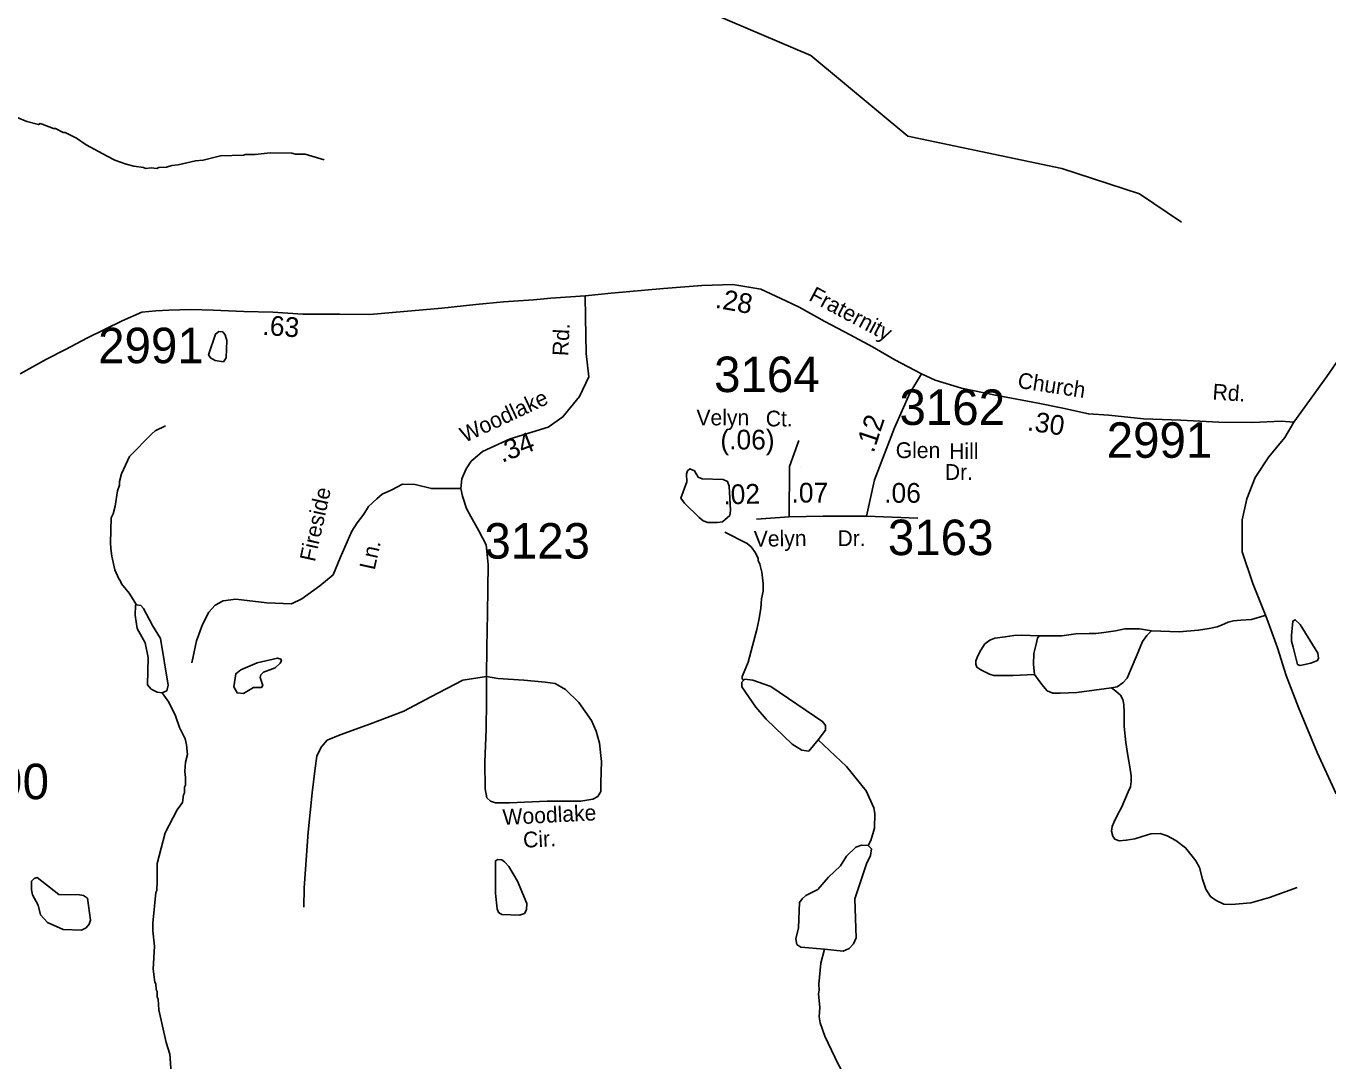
# Model space of a CAD drawing. Extents: x 1551653 to 1702041, y 811336 to 920032.
# Drawn here: x 1609613 to 1615028, y 824369 to 828674 of the extents above; entities that cross this region are included whole.
import ezdxf

# ---------------------------------------------------------------- set-up
doc = ezdxf.new("R2010")
doc.units = 0
for name, color, linetype in [('Old_Level_10', 7, 'Continuous'), ('Old_Level_11', 7, 'Continuous'), ('Old_Level_17', 7, 'Continuous'), ('Old_Level_32', 7, 'Continuous'), ('Old_Level_35', 7, 'Continuous'), ('Old_Level_59', 7, 'Continuous'), ('Old_Level_62', 7, 'Continuous'), ('Old_Level_8', 7, 'Continuous')]:
    doc.layers.add(name, color=color, linetype=linetype)

msp = doc.modelspace()

# ---------------------------------------------------------------- linework, layer by layer
at = {"layer": 'Old_Level_17'}
msp.add_line((1612833.711, 826837.728), (1612833.711, 826837.728), dxfattribs=at)
at = {"layer": 'Old_Level_32'}
for p, q in [((1612787.219, 826632.516), (1612651.564, 826622.461)), ((1613322.303, 826627.489), (1613108.771, 826635.03))]:
    msp.add_line(p, q, dxfattribs=at)
for points in [[(1615872.117, 828613.906), (1615854.48, 828536.257), (1615829.788, 828455.078), (1615794.515, 828359.782), (1615745.132, 828260.956), (1615678.112, 828169.189), (1615589.928, 828063.303), (1615494.689, 827904.476), (1615427.669, 827798.591), (1615367.704, 827696.236), (1615311.266, 827618.586), (1615247.773, 827540.937), (1615180.753, 827445.641), (1615022.93, 827216.627), (1614886.031, 827027.073)], [(1611938.181, 827552.387), (1612046.323, 827562.996), (1612264.726, 827582.091), (1612423.757, 827594.821), (1612552.228, 827599.231), (1612668.615, 827580.229), (1612772.516, 827531.429), (1612828.185, 827505.142), (1612935.979, 827444.947), (1613041.03, 827389.205), (1613134.284, 827340.088), (1613226.234, 827285.186), (1613337.763, 827228.028)], [(1609589.303, 827228.028), (1609698.111, 827287.909), (1609776.997, 827328.737), (1609869.485, 827377.731), (1610013.657, 827448.499), (1610095.263, 827483.884), (1610152.388, 827489.327), (1610206.792, 827492.05), (1610299.28, 827494.771), (1610391.767, 827492.05), (1610519.617, 827486.606), (1610639.307, 827483.884), (1610764.437, 827475.718), (1610916.657, 827476.121), (1611042.494, 827474.569), (1611184.416, 827486.699), (1611342.385, 827500.704), (1611484.206, 827516.546), (1611598.914, 827526.926), (1611724.019, 827535.413), (1611796.113, 827541.779), (1611938.181, 827552.387)], [(1611938.181, 827552.387), (1611940.302, 827463.276), (1611942.422, 827312.635), (1611953.695, 827214.515), (1611914.539, 827132.878), (1611846.035, 827048.437), (1611784.543, 827006.003), (1611627.393, 826956.542), (1611511.101, 826904.515), (1611480.557, 826878.17), (1611464.679, 826864.13), (1611443.475, 826832.304), (1611425.086, 826790.003), (1611421.585, 826750.94), (1611428.614, 826717.913), (1611444.801, 826667.296), (1611463.548, 826634.498), (1611496.873, 826574.481), (1611526.277, 826515.899), (1611535.221, 826433.872), (1611532.766, 826231.606), (1611529.503, 826087.925), (1611528.228, 825969.08)], [(1613337.763, 827228.028), (1613288.799, 827146.371), (1613225.698, 827003.045), (1613141.43, 826785.849), (1613108.771, 826635.03)], [(1613337.763, 827228.028), (1613394.887, 827200.808), (1613503.696, 827168.146), (1613645.148, 827138.206), (1613822.284, 827104.82), (1613925.884, 827084.458), (1614031.333, 827060.394), (1614116.433, 827054.84), (1614260.733, 827040.031), (1614416.132, 827034.478), (1614573.381, 827027.073), (1614713.981, 827025.222), (1614834.231, 827030.776), (1614886.031, 827027.073)], [(1614886.031, 827027.073), (1614849.03, 826963.024), (1614782.431, 826881.575), (1614725.081, 826796.424), (1614689.931, 826707.57), (1614671.432, 826620.568), (1614671.432, 826487.288), (1614715.831, 826355.858), (1614773.641, 826209.821), (1614817.978, 826087.253), (1614854.481, 825972.85), (1614905.849, 825840.126), (1614982.745, 825651.615), (1615061.564, 825480.416)], [(1612787.219, 826632.516), (1612789.028, 826842.25), (1612827.061, 826950.792)], [(1613108.771, 826635.03), (1612927.898, 826635.03), (1612787.219, 826632.516)]]:
    msp.add_lwpolyline(points, dxfattribs=at)
at = {"layer": 'Old_Level_35'}
for points in [[(1610302.502, 826024.762), (1610321.57, 826116.426), (1610346.557, 826184.158), (1610373.013, 826235.651), (1610399.431, 826265.33), (1610433.604, 826282.849), (1610485.582, 826290.198), (1610615.316, 826275.138), (1610716.996, 826271.194), (1610760.803, 826291.74), (1610834.48, 826345.898), (1610889.951, 826391.615), (1610920.197, 826461.39), (1610968.11, 826572.341), (1610990.116, 826607.486), (1611017.495, 826643.1), (1611038.065, 826675.454), (1611072.289, 826706.959), (1611093.813, 826726.675), (1611134.881, 826744.481), (1611179.044, 826768.255), (1611231.064, 826766.885), (1611299.511, 826750.448), (1611421.585, 826750.94)], [(1614770.826, 826223.843), (1614709.771, 826206.079), (1614665.15, 826202.073), (1614634.81, 826199.419), (1614613.308, 826194.72), (1614584.427, 826181.336), (1614566.429, 826174.752), (1614534.203, 826168.592), (1614489.476, 826161.026), (1614409.179, 826154.527), (1614293.579, 826157.99)], [(1614293.579, 826157.99), (1614243.996, 826166.6), (1614222.654, 826167.239), (1614183.475, 826166.632), (1614144.082, 826158.907), (1614095.797, 826151.448), (1614061.847, 826147.121), (1614035.17, 826147.921), (1613979.931, 826146.013), (1613920.922, 826137.094), (1613826.611, 826138.139)], [(1614128.046, 825920.715), (1614151.325, 825925.361), (1614174.978, 825942.464), (1614193.349, 825961.506), (1614206.811, 825994.944), (1614233.683, 826060.04), (1614256.677, 826114.567), (1614275.208, 826138.948), (1614293.579, 826157.99)], [(1613826.611, 826138.139), (1613751.916, 826140.377), (1613721.629, 826139.503), (1613685.846, 826133.451), (1613642.95, 826127.611), (1613621.342, 826119.353), (1613601.299, 826103.923), (1613584.493, 826077.709), (1613571.351, 826054.949), (1613563.598, 826033.807), (1613563.171, 826019.571), (1613568.133, 826006.954), (1613583.82, 825995.798), (1613620.687, 825978.663), (1613638.312, 825972.791), (1613661.432, 825972.099), (1613716.617, 825972.227), (1613807.532, 825976.627)], [(1613807.532, 825976.627), (1613803.476, 826019.496), (1613804.808, 826063.984), (1613814.874, 826102.868), (1613819.177, 826127.675), (1613826.611, 826138.139)], [(1610768.761, 825009.341), (1610769.784, 825089.364), (1610786.687, 825320.952), (1610802.819, 825484.718), (1610816.09, 825586.505), (1610822.704, 825636.397), (1610841.277, 825674.041), (1610865.693, 825703.766), (1610919.754, 825725.081), (1611046.158, 825771.344), (1611184.692, 825823.565), (1611297.382, 825884.113), (1611430.236, 825952.459), (1611528.228, 825969.08)], [(1611528.228, 825969.08), (1611576.079, 825960.507), (1611683.785, 825953.119), (1611771.652, 825944.133), (1611813.578, 825939.481), (1611857.105, 825914.983), (1611912.43, 825860.432), (1611965.343, 825785.718), (1611984.857, 825741.495), (1611998.046, 825691.4), (1612007.105, 825615.177), (1612003.925, 825527.391), (1612003.555, 825489.376), (1611991.147, 825469.616), (1611971.097, 825457.818), (1611921.12, 825450.426), (1611781.242, 825450.262), (1611623.395, 825442.257), (1611565.38, 825443.035), (1611545.098, 825449.449), (1611529.773, 825463.366), (1611522.142, 825501.542), (1611521.571, 825611.417), (1611527.371, 825749.376), (1611528.92, 825865.209), (1611528.228, 825969.08)], [(1613807.532, 825976.627), (1613838.317, 825934.739), (1613860.691, 825909.132), (1613883.544, 825899.542), (1613913.778, 825898.636), (1613983.298, 825901.897), (1614128.046, 825920.715)], [(1614128.046, 825920.715), (1614145.457, 825907.725), (1614164.54, 825891.123), (1614174.678, 825873.008), (1614179.373, 825851.493), (1614180.192, 825819.409), (1614180.211, 825760.631), (1614187.131, 825694.521), (1614196.159, 825639.393), (1614203.664, 825592.858), (1614209.658, 825555.274), (1614208.965, 825532.14), (1614206.494, 825509.06), (1614196.962, 825487.972), (1614170.197, 825426.434), (1614151.293, 825389.596), (1614137.991, 825361.497), (1614130.344, 825343.915), (1614127.979, 825324.393), (1614132.728, 825304.658), (1614141.247, 825291.935), (1614158.819, 825284.284), (1614189.159, 825286.938), (1614224.941, 825292.99), (1614255.495, 825302.761), (1614291.437, 825314.153), (1614330.616, 825314.76), (1614358.805, 825305.009), (1614395.619, 825286.095), (1614435.649, 825255.686), (1614457.969, 825228.3), (1614478.511, 825200.967), (1614493.717, 825173.795), (1614506.505, 825125.321), (1614519.507, 825083.965), (1614539.942, 825053.074), (1614562.582, 825036.366), (1614594.167, 825021.17), (1614626.18, 825020.211), (1614706.477, 825026.711)], [(1614706.477, 825026.711), (1614785.119, 825049.29), (1614900.274, 825090.369)]]:
    msp.add_lwpolyline(points, dxfattribs=at)
at = {"layer": 'Old_Level_59'}
msp.add_lwpolyline([(1614418.729, 827857.802), (1614244.742, 827976.219), (1613920.657, 828081.258), (1613280.69, 828215.669), (1612876.737, 828552.108), (1612271.731, 828810.628), (1612074.676, 829021.422), (1611787.705, 829391.591), (1611415.741, 829665.028), (1611042.649, 829820.355), (1610759.677, 829865.467), (1610619.729, 829933.954), (1610330.708, 830205.7), (1610132.73, 830308.226), (1609659.675, 830472.113)], dxfattribs=at)
at = {"layer": 'Old_Level_62'}
for points in [[(1610853.796, 828117.962), (1610774.133, 828141.081), (1610734.148, 828141.594), (1610718.256, 828145.849), (1610628.341, 828147.079), (1610566.21, 828139.953), (1610526.225, 828140.518), (1610518.228, 828136.622), (1610422.264, 828133.956), (1610350.085, 828116.988), (1610317.995, 828113.451), (1610245.816, 828096.432), (1610219.877, 828094.791), (1610197.732, 828087.102), (1610165.743, 828085.564), (1610157.644, 828081.668), (1610133.755, 828084.026), (1610109.764, 828082.334), (1610101.767, 828086.435), (1610061.885, 828090.998), (1610029.999, 828099.456), (1609982.222, 828116.117), (1609950.541, 828132.572), (1609863.189, 828179.734), (1609823.614, 828208.287), (1609775.939, 828230.946), (1609767.942, 828231.048), (1609736.159, 828247.503), (1609728.162, 828247.606), (1609680.488, 828266.266), (1609672.491, 828268.368), (1609664.494, 828264.523), (1609616.716, 828277.185), (1609576.936, 828293.743)], [(1610448.818, 827365.831), (1610442.051, 827390.027), (1610431.081, 827402.638), (1610415.394, 827403.304), (1610400.938, 827392.795), (1610372.641, 827306.468), (1610379.92, 827293.396), (1610399.708, 827282.99), (1610434.362, 827277.966), (1610445.64, 827294.063), (1610448.818, 827365.831)], [(1610193.015, 827011.449), (1610150.775, 826990.021), (1610136.626, 826978.231), (1610043.43, 826883.549), (1610010.416, 826812.036), (1610002.009, 826780.151), (1610001.804, 826764.157), (1609993.5, 826740.268), (1609984.58, 826676.394), (1609976.173, 826644.56), (1609967.971, 826628.669), (1609964.587, 826524.707), (1609966.228, 826500.716), (1609969.816, 826468.676), (1609983.042, 826412.492), (1609998.523, 826374.302), (1610004.367, 826368.201), (1610010.211, 826354.155), (1610041.687, 826315.708), (1610072.957, 826266.752)], [(1612412.192, 826630.258), (1612429.108, 826616.314), (1612448.281, 826609.445), (1612488.573, 826609.547), (1612509.591, 826612.06), (1612540.144, 826638.204), (1612543.63, 826658.555), (1612537.068, 826759.595), (1612530.096, 826780.1), (1612513.077, 826787.994), (1612425.52, 826790.096), (1612408.501, 826798.042), (1612393.327, 826824.134), (1612374.052, 826832.08), (1612364.107, 826823.878), (1612360.108, 826811.268), (1612360.826, 826778.152), (1612336.937, 826710.587), (1612352.111, 826689.415), (1612412.192, 826630.258)], [(1612519.639, 826569.101), (1612612.938, 826521.785), (1612628.727, 826507.586), (1612646.361, 826483.338), (1612658.049, 826459.193), (1612657.946, 826451.196), (1612665.738, 826435.1), (1612673.325, 826403.009), (1612678.657, 826354.924), (1612678.247, 826322.936), (1612671.787, 826291.051), (1612669.224, 826251.065), (1612660.612, 826203.237), (1612652, 826163.354), (1612616.218, 826027.866), (1612599.712, 825988.137), (1612591.305, 825968.299), (1612591.202, 825960.045), (1612597.251, 825951.074)], [(1610072.957, 826266.752), (1610067.831, 826264.855), (1610066.703, 826223.383), (1610075.213, 826167.763), (1610108.329, 826108.297), (1610121.042, 826046.987), (1610119.094, 825933.747), (1610133.653, 825916.01), (1610158.156, 825903.092), (1610178.969, 825900.58)], [(1610178.969, 825900.58), (1610198.244, 825908.987), (1610204.088, 825932.107), (1610172.51, 826126.547), (1610138.677, 826180.373), (1610101.46, 826251.116), (1610091.104, 826263.881), (1610072.957, 826266.752)], [(1614883.274, 826090.663), (1614901.319, 826018.69), (1614912.084, 826014.076), (1614956.99, 826023.406), (1614984.467, 826034.786), (1614988.158, 826044.629), (1614985.288, 826065.749), (1614912.084, 826184.116), (1614891.681, 826204.569), (1614881.326, 826198.828), (1614875.79, 826139.209), (1614875.892, 826115.884), (1614883.274, 826090.663)], [(1610574.207, 826025.661), (1610506.745, 825996.288), (1610485.112, 825979.627), (1610477.73, 825924.93), (1610490.648, 825900.119), (1610517.1, 825897.043), (1610559.751, 825922.162), (1610592.662, 825922.674), (1610598.198, 825930.877), (1610587.638, 825964.3), (1610589.996, 825975.68), (1610600.249, 825987.009), (1610649.256, 826003.773), (1610670.377, 826023.201), (1610675.093, 826033.198), (1610672.427, 826040.989), (1610658.791, 826045.244), (1610574.207, 826025.661)], [(1612908.315, 825704.602), (1612868.33, 825657.645), (1612839.418, 825662.361), (1612799.227, 825686.505), (1612691.575, 825790.467), (1612648.206, 825840.141), (1612590.382, 825925.135), (1612590.587, 825944.461), (1612597.251, 825951.074)], [(1612597.251, 825951.074), (1612602.992, 825956.611), (1612636.313, 825953.586), (1612711.465, 825927.288), (1612926.667, 825779.907), (1612938.765, 825763.964), (1612938.56, 825745.56), (1612908.315, 825704.602)], [(1610178.969, 825900.58), (1610207.369, 825861.517), (1610234.538, 825805.128), (1610251.865, 825756.89), (1610275.241, 825708.6), (1610280.88, 825684.506), (1610284.366, 825644.47), (1610275.959, 825612.584), (1610273.396, 825572.651), (1610277.087, 825548.608), (1610276.574, 825516.62), (1610272.473, 825508.674), (1610272.165, 825484.683), (1610268.064, 825476.737), (1610263.656, 825444.801), (1610241.203, 825413.12), (1610191.99, 825317.873), (1610158.259, 825190.331), (1610159.284, 825118.358), (1610156.721, 825078.372), (1610152.62, 825070.478), (1610140.83, 824942.628), (1610140.419, 824910.64), (1610147.494, 824846.561), (1610142.265, 824750.699), (1610149.442, 824696.566), (1610153.44, 824690.516), (1610155.081, 824666.525), (1610158.977, 824658.477), (1610158.669, 824634.486), (1610162.565, 824626.438), (1610165.948, 824582.402), (1610196.091, 824445.992), (1610211.368, 824397.805), (1610218.032, 824301.738)], [(1612908.315, 825704.602), (1613025.605, 825594.386), (1613107.831, 825492.423), (1613138.691, 825421.835), (1613143.715, 825398.049), (1613142.177, 825337.507), (1613126.695, 825285.834), (1613115.008, 825265.79)], [(1613115.008, 825265.79), (1613087.838, 825266.969), (1613064.975, 825258.459), (1613024.99, 825221.14), (1613000.896, 825181.001), (1612951.273, 825134.147), (1612905.854, 825081.961), (1612856.437, 825057.918), (1612841.366, 825044.026), (1612830.703, 825028.34), (1612826.089, 824922.994), (1612814.094, 824876.601), (1612818.297, 824853.738), (1612835.727, 824842.973), (1612934.152, 824833.489)], [(1612934.152, 824833.489), (1613011.046, 824826.056), (1613036.678, 824836.309), (1613055.235, 824856.301), (1613066.103, 824881.676), (1613059.951, 825043.309), (1613108.036, 825189.459), (1613125.978, 825224.37), (1613128.951, 825251.59), (1613115.008, 825265.79)], [(1611657.702, 825116.46), (1611621.101, 825177.515), (1611603.261, 825198.071), (1611591.676, 825206.376), (1611574.861, 825206.581), (1611566.044, 825201.404), (1611566.352, 825066.223), (1611571.991, 825001.529), (1611577.732, 824986.868), (1611592.188, 824977.999), (1611666.11, 824976), (1611685.897, 824982.767), (1611694.817, 824998.402), (1611695.74, 825024.597), (1611657.702, 825116.46)], [(1609767.942, 824915.971), (1609703.043, 824944.473), (1609673.516, 824977.435), (1609664.186, 825017.83), (1609640.4, 825059.764), (1609635.786, 825081.346), (1609636.196, 825116.768), (1609646.654, 825128.456), (1609659.88, 825131.789), (1609749.385, 825062.019), (1609835.405, 825060.328), (1609852.731, 825057.355), (1609868.623, 825046.077), (1609880.824, 824954.264), (1609876.415, 824937.655), (1609863.087, 824923.199), (1609844.222, 824913.716), (1609767.942, 824915.971)], [(1612934.152, 824833.489), (1612918.978, 824775.972), (1612909.75, 824688.107), (1612911.391, 824664.065), (1612909.238, 824648.122), (1612914.467, 824592.04), (1612911.903, 824552.106), (1612915.594, 824528.064), (1612934.767, 824471.828), (1612991.156, 824355.051), (1613014.635, 824314.707), (1613070.716, 824177.989), (1613103.832, 824117.549), (1613115.418, 824085.356), (1613162.067, 823992.724), (1613191.082, 823920.341), (1613206.461, 823872.154), (1613217.739, 823824.017), (1613221.327, 823791.978), (1613225.223, 823783.93), (1613224.608, 823735.947), (1613239.577, 823663.769), (1613241.525, 823605.381)]]:
    msp.add_lwpolyline(points, dxfattribs=at)

# ---------------------------------------------------------------- texts
at = {"layer": 'Old_Level_10'}
for s, rotation, p in [('Fireside', 77.528453, (1610814.59, 826442.852)), ('Ln.', 77.528453, (1611062.975, 826408.584)), ('Woodlake', 2.903267, (1611596.735, 825350.603)), ('Cir.', 2.903267, (1611682.005, 825255.88))]:
    msp.add_text(s, height=65.6167, rotation=rotation, dxfattribs=at).set_placement(p)
at = {"layer": 'Old_Level_11'}
for s, rotation, p in [('Fraternity', 332.033125, (1612864.798, 827535.466)), ('Rd.', 87.028192, (1611867.672, 827300.118)), ('Church', 351.230319, (1613734.139, 827169.608)), ('Woodlake', 25.08, (1611437.606, 826939.786)), ('Rd.', 356.011328, (1614546.142, 827121.179)), ('Velyn', 0.766433, (1612640.242, 826508.195))]:
    msp.add_text(s, height=65.6167, rotation=rotation, dxfattribs=at).set_placement(p)
for s, p in [('Velyn', (1612401.417, 827013.02)), ('Ct.', (1612689.652, 827008.696)), ('Glen', (1613230.239, 826877.079)), ('Hill', (1613452.551, 826872.755)), ('Dr.', (1613434.584, 826786.287)), ('Dr.', (1612987.989, 826510.839))]:
    msp.add_text(s, height=65.6167, dxfattribs=at).set_placement(p)
at = {"layer": 'Old_Level_17'}
for s, rotation, p in [('.28', 349.840689, (1612476.253, 827502.917)), ('.63', 355.887897, (1610594.552, 827389.911)), ('.12', 71.801714, (1613137.807, 826895.252)), ('.30', 351.316869, (1613774.463, 826993.002)), ('.34', 21.112383, (1611592.614, 826857.052)), ('(.06)', 359.927997, (1612500.935, 826913.015)), ('.02', 1.489811, (1612514.342, 826684.073)), ('.07', 0.097883, (1612796.909, 826692.014))]:
    msp.add_text(s, height=82.0208, rotation=rotation, dxfattribs=at).set_placement(p)
msp.add_text('.06', height=82.0208, dxfattribs=at).set_placement((1613182.323, 826691.27))
at = {"layer": 'Old_Level_8'}
for s, p in [('2991', (1609913.121, 827271.642)), ('3164', (1612474.731, 827151.566)), ('3162', (1613245.823, 827014.765)), ('2991', (1614107.602, 826878.155)), ('3123', (1611519.374, 826458.819)), ('3163', (1613197.543, 826473.284)), ('2990', (1609269.68, 825457.885))]:
    msp.add_text(s, height=147.6375, dxfattribs=at).set_placement(p)

doc.saveas('drawing.dxf')
